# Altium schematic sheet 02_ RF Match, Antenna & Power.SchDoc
size 420 x 297 mm; SheetNumber: 2; SheetTotal: 4
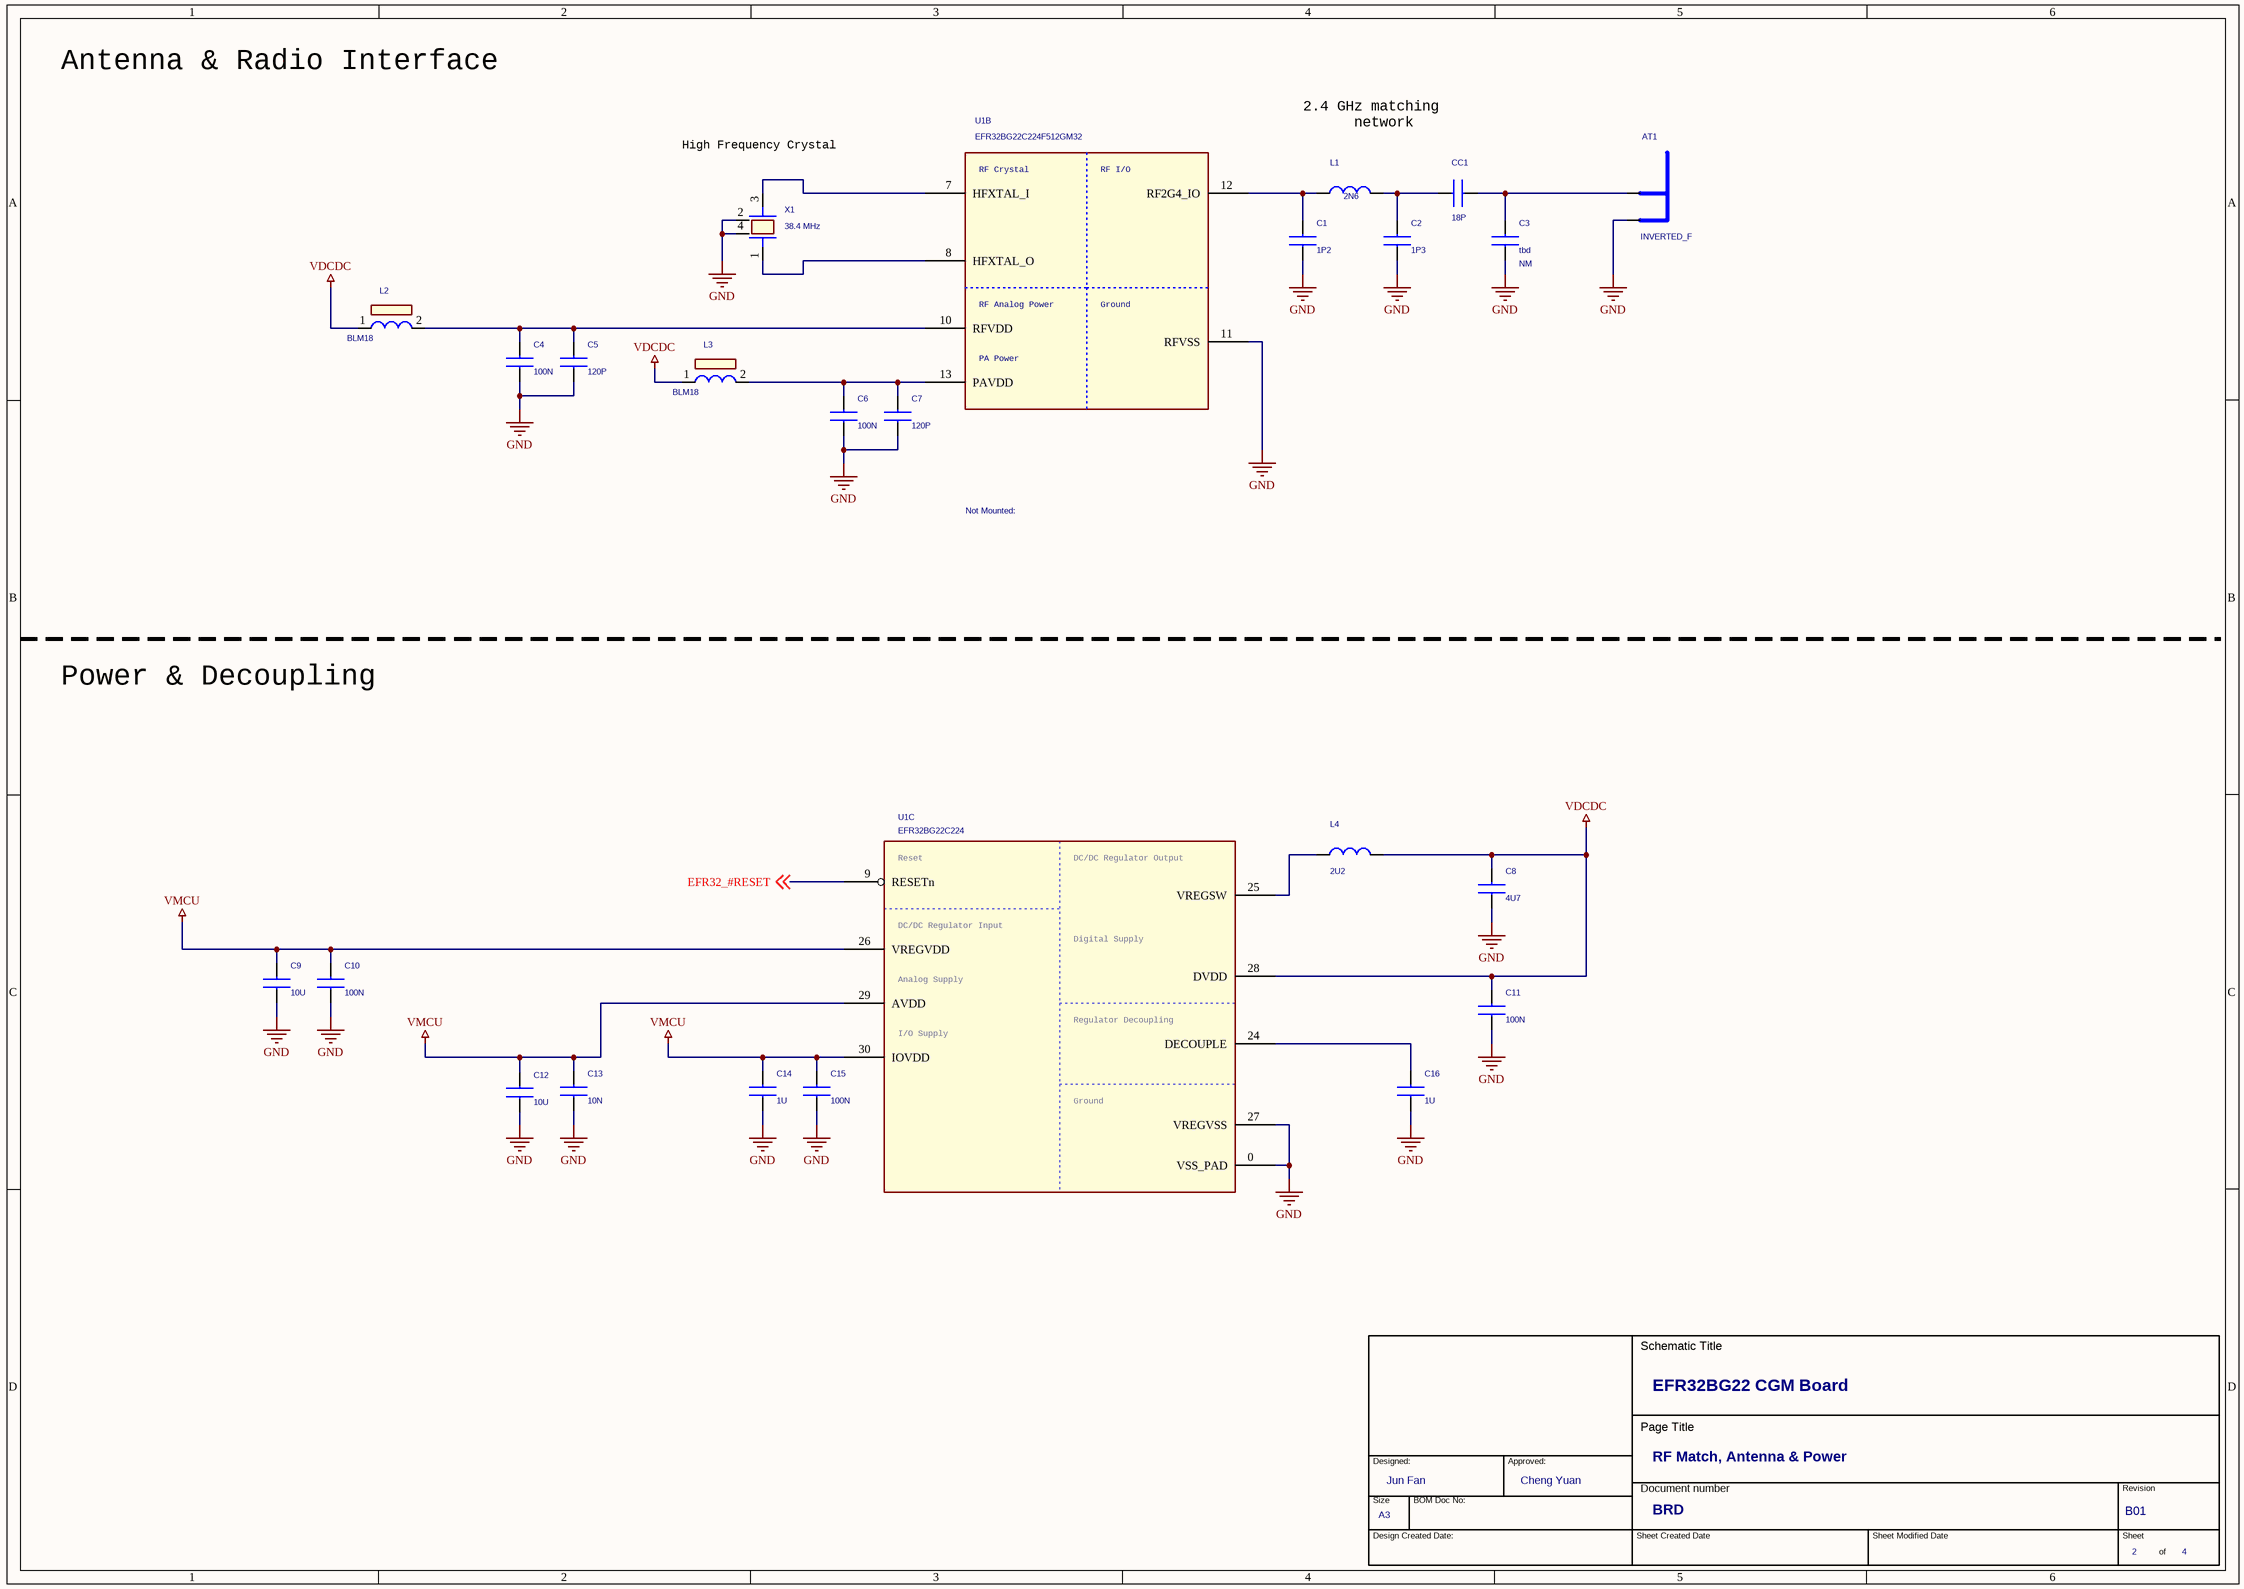
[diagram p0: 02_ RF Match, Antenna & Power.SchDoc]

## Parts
*?  OrgAddr2: Cheng Yuan  OrgAddr1: Jun Fan  Page Count: 4  Page Number: 2  Doc: BRD  Title: EFR32BG22 CGM Board  RevCode: B01  Page Size: A3  Page Title: RF Match, Antenna & Power  (hidden comment: TitleBlock_SiLabs_A3)  (graphical)
AT1  INVERTED_F  [EM358x_INVERTED_F]  (net tie, no BOM)
C1  1P2  [C0201_L]
C2  1P3  [C0201_L]
C3  tbd  Not Mounted: NM  [C0201_L]
C4  100N  [C0201_L]
C5  120P  [C0201_L]
C6  100N  [C0201_L]
C7  120P  [C0201_L]
C8  4U7  [C0603_L]
C9  10U  [C0603_L]
C10  100N  [C0201_L]
C11  100N  [C0201_L]
C12  10U  [C0603_L]
C13  10N  [C0201_L]
C14  1U  [C0402_L]
C15  100N  [C0201_L]
C16  1U  [C0402_L]
CC1  18P  [C0201_L]
L1  2N6  [COIL_0201_L]
L2  BLM18  [COIL_MUR_BLM18_0603]
L3  BLM18  [COIL_MUR_BLM18_0603]
L4  2U2  [COIL_1008_L]
U1  EFR32BG22C224F512GM32  [QFN32_M040_4.0X4.0_EP_SL]  (parts B,C of 3)
X1  38.4 MHz  [KDS_DSX211SH_2016]

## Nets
GND: AT1.2(GND) C1.2 C2.2 C3.2 C4.2 C5.2 C6.2 C7.2 C8.2 C9.2 C10.2 C11.2 C12.2 C13.2 C14.2 C15.2 C16.2 U1.0(VSS_PAD) U1.11(RFVSS) U1.27(VREGVSS) X1.2 X1.4
VDCDC: C8.1 C11.1 L2.1 L3.1 L4.2 U1.28(DVDD)
VMCU: C9.1 C10.1 C12.1 C13.1 C14.1 C15.1 U1.26(VREGVDD) U1.29(AVDD) U1.30(IOVDD)
EFR32_#RESET: U1.9(RESETn) ; off-sheet EFR32_#RESET
NetAT1_1: AT1.1(ANT) C3.1 CC1.2
NetC1_1: C1.1 L1.1 U1.12(RF2G4_IO)
NetC2_1: C2.1 CC1.1 L1.2
NetC4_1: C4.1 C5.1 L2.2 U1.10(RFVDD)
NetC6_1: C6.1 C7.1 L3.2 U1.13(PAVDD)
NetC16_1: C16.1 U1.24(DECOUPLE)
NetL4_1: L4.1 U1.25(VREGSW)
NetU1_7: U1.7(HFXTAL_I) X1.3
NetU1_8: U1.8(HFXTAL_O) X1.1

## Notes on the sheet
- Antenna & Radio Interface
- High Frequency Crystal
- 2.4 GHz matching
  network
- Power & Decoupling

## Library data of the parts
*? = TitleBlock_SiLabs_A3: Cage Code: <Cage Code>
C1 = C0201: Tolerance: ±0.05P; Mfg: Murata; Mfg #: GRM0335C1H1R2WA01D
C2 = C0201: Tolerance: ±0.1P; Mfg: Murata; Mfg #: GRM0335C1H1R3BA01D
C3 = C0201: Tolerance: ±0.1P; Mfg: Murata
C4 C6 C10 C11 C15 = C0201: Rating: 25V; Tolerance: 10%
C5 C7 = C0201: Rating: 50V; Tolerance: 5%
C8 = C0603: Rating: 6.3V; Tolerance: 20%
C9 C12 = C0603: Rating: 25V; Tolerance: 20%
C13 = C0201: Rating: 10V; Tolerance: 10%
C14 C16 = C0402: Rating: 25V; Tolerance: 10%
CC1 = C0201: Tolerance: ±2%; Mfg: Murata; Mfg #: GJM0335C1E180GB01D
L1 = L0201: Tolerance: ±0.1N; Mfg #: LQP03HQ2N6B02; Mfg: Murata
L2 L3 = BLM21B102S: Mfg #: BLM18AG102SN1; Mfg: Murata
L4 = L1008: Mfg: Samsung; Mfg #: CIG22H2R2MNE; Tolerance: +/-20%
U1 = EFR32xG22_QFN32_2G4: MFG: Silicon Labs; MFG #: EFR32BG22C224F512IM32
X1 = DSX211SH: Mfg: Tai-Saw Technology; Mfg #: TZ3398B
